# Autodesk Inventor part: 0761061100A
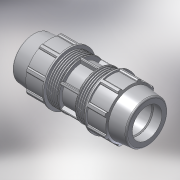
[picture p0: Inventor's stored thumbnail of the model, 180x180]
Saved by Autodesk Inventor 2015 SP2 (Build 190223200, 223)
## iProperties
Created: 2017-02
Part Number: 0761061100A
Material: PVC-Piping
Description: PLASSON REPAIR COUPLER 110
Document SubType Name: Modeling
Designer: KIM
Mass: 2387.75 g
Surface Area: 2478.17 cm^2
Volume: 1705.54 cm^3
Density: 1.4 g/cm^3
Appearance: Smooth - White
Author: KIM
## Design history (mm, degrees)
derived "87610.ipt"
feature "Solid1::87610.ipt"
tag "TaggingFeature1"
body "Solid1"
other parameters: "d1" = 393, "d4" = 32.75, "d5" = 56.14286, "d7" = 181, "d8" = 135.75, "d9" = 56.14286, "d11" = 5.61429, "d12" = 144.8, "d13" = 120 deg, "d14" = 143, "d15" = 6 deg, "d16" = 162.9, "d18" = 5.5, "d19" = 35 deg, "d20" = 17.5 deg, "d21" = 168.33, "d23" = 0, "d25" = 360 deg, "d27" = 3.62, "d33" = 2.2, "d34" = 9.05, "d36" = 0, "d37" = 2.2, "d38" = 2.2, "d40" = 360 deg, "d42" = 70.74, "d46" = 3.3, "d50" = 4.9125, "d51" = 0, "d53" = 3.59314, "d54" = 3.59314, "d57" = 7.18629, "d62" = 159.642, "E_" = 181, "H_" = 393, "l_" = 143, "d52" = 35.93143
